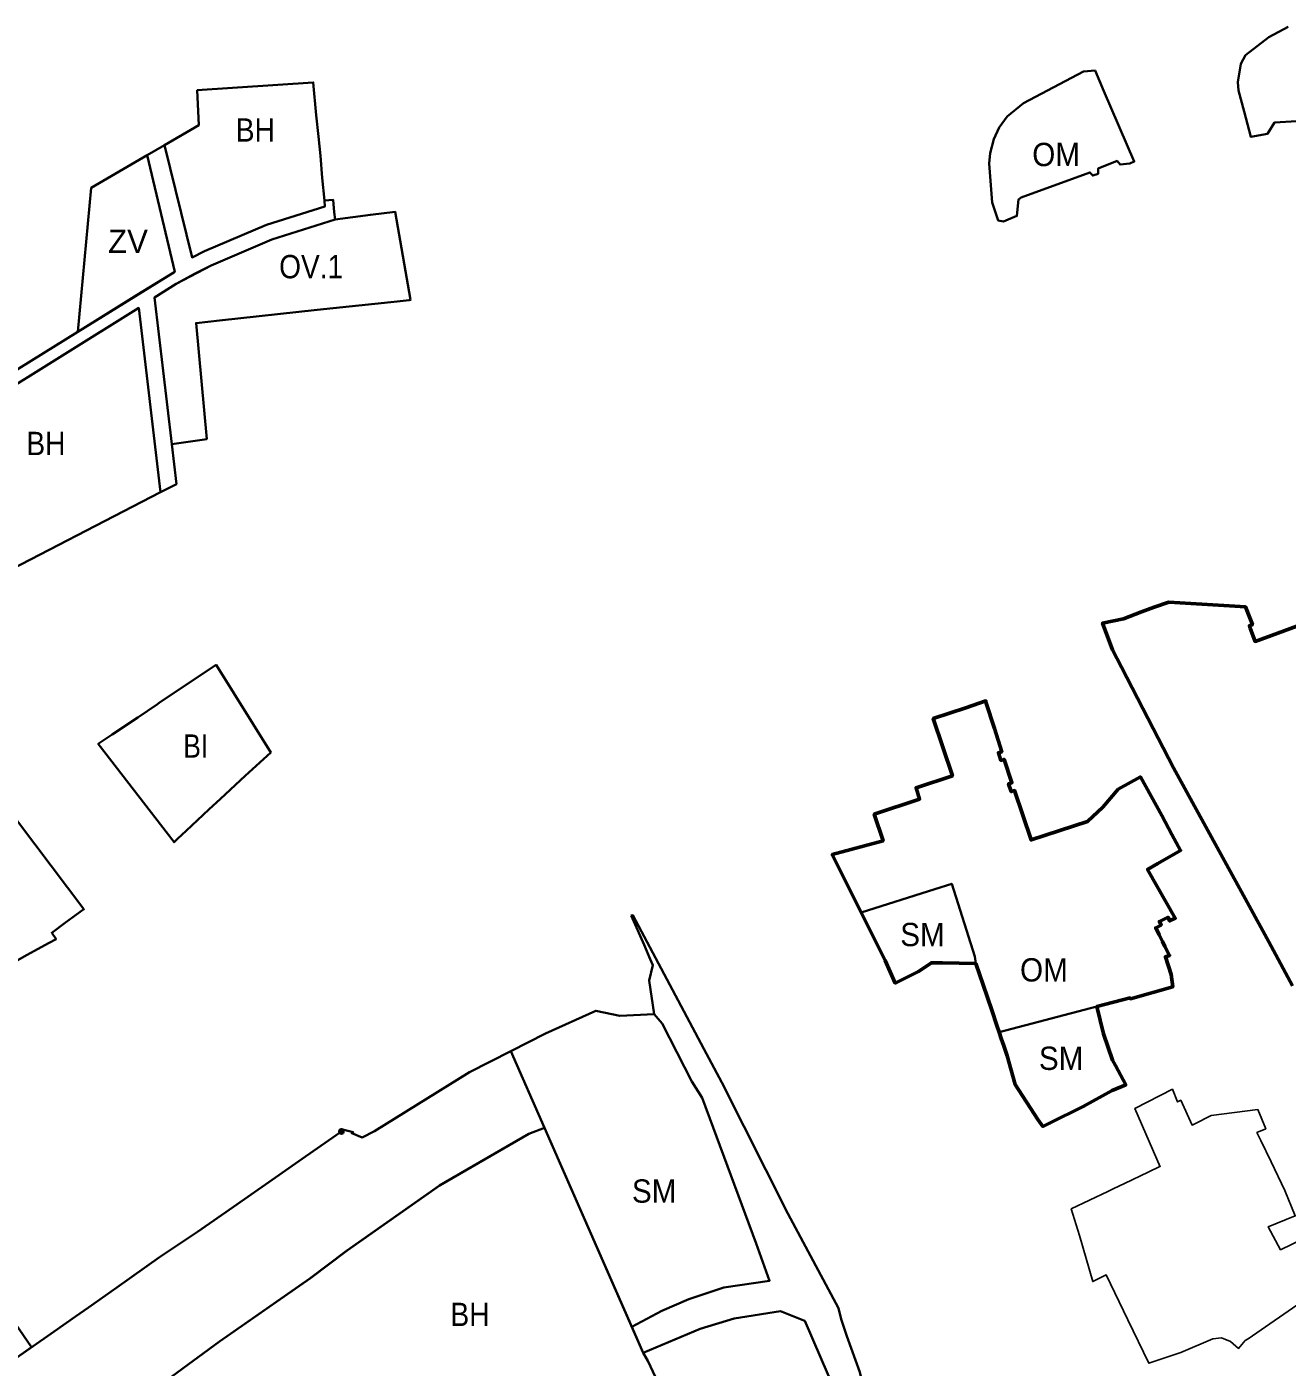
# Model space of a CAD drawing. Extents: x -650276 to -642489, y -1074311 to -1066658.
# Drawn here: x -648077 to -647428, y -1071063 to -1070373 of the extents above; entities that cross this region are included whole.
import ezdxf

# ---------------------------------------------------------------- set-up
doc = ezdxf.new("R2010")
doc.units = 0
doc.header["$LTSCALE"] = 4.8
doc.header["$PDMODE"] = 32
doc.header["$PDSIZE"] = 2.4
for name, color, linetype, lineweight in [('1', 7, 'Continuous', 35), ('11', 7, 'Continuous', 35), ('12', 7, 'Continuous', 35), ('15', 7, 'Continuous', 35), ('17', 7, 'Continuous', 35), ('18', 7, 'Continuous', 35), ('2', 7, 'Continuous', 35), ('40', 7, 'Continuous', 35), ('60', 7, 'Continuous', 53), ('61', 7, 'Continuous', 25)]:
    doc.layers.add(name, color=color, linetype=linetype, lineweight=lineweight)
doc.layers.add('62', color=7, linetype='Continuous')

msp = doc.modelspace()

# ---------------------------------------------------------------- linework, layer by layer
at = {"layer": '1'}
for points in [[(-647991.539, -1070492.016), (-647985.19, -1070488.804), (-647953.251, -1070475.276), (-647923.247, -1070465.749), (-647923.53, -1070462.75), (-647924.63, -1070451.09), (-647925.5, -1070439.63), (-647926.53, -1070429.76), (-647927.67, -1070418.74), (-647929.24, -1070401.97), (-647988.86, -1070405.95), (-647988.11, -1070423.93), (-648005.668, -1070434.145)], [(-648098.637, -1070659.682), (-648007.838, -1070612.851), (-648019, -1070518), (-648135.47, -1070590.61), (-648105.98, -1070645.91)], [(-648001.922, -1071067.83), (-647977.41, -1071049.74), (-647930.7, -1071017.18), (-647911.838, -1071002.919), (-647864.03, -1070969.3), (-647864.03, -1070969.3), (-647818.33, -1070942.91), (-647810.243, -1070939.825), (-647759.52, -1071055.67), (-647757.19, -1071059.66), (-647742.64, -1071090.72), (-647726.74, -1071122.48), (-647742.35, -1071129.43), (-647775.982, -1071148.001), (-647775.982, -1071148.001), (-647875.939, -1071221.104)]]:
    msp.add_lwpolyline(points, close=True, dxfattribs=at)
at = {"layer": '11'}
msp.add_lwpolyline([(-647927.14, -1070519), (-647889.27, -1070514.92), (-647886.09, -1070514.58), (-647879.89, -1070513.91), (-647879.16, -1070513.83), (-647887.08, -1070468.54), (-647899.87, -1070470.04), (-647917.98, -1070472.47), (-647950.48, -1070482.79), (-647981.81, -1070496.06), (-647990.295, -1070500.352), (-647999.756, -1070505.655), (-648010.831, -1070512.588), (-648002, -1070588), (-647984.03, -1070585.46), (-647989.5, -1070525.73), (-647977.41, -1070524.43)], close=True, dxfattribs=at)
at = {"layer": '12'}
msp.add_lwpolyline([(-647515.73, -1070442.32), (-647514.23, -1070444.18), (-647509.22, -1070443.62), (-647506.95, -1070442.71), (-647522.54, -1070406.51), (-647527.1, -1070395.72), (-647533.1, -1070396.26), (-647564.01, -1070412.59), (-647572.37, -1070419.41), (-647576.48, -1070425.09), (-647579.22, -1070431.05), (-647581.04, -1070438.4), (-647581.54, -1070443.7), (-647580.1, -1070463.69), (-647576.92, -1070473), (-647574.28, -1070473.46), (-647567.32, -1070470.66), (-647566.55, -1070462.22), (-647565.11, -1070461.12), (-647529.74, -1070448.27), (-647528.28, -1070449.87), (-647525.54, -1070448.89), (-647525.45, -1070446.21)], close=True, dxfattribs=at)
msp.add_lwpolyline([(-647515.73, -1070442.32), (-647514.23, -1070444.18), (-647509.22, -1070443.62), (-647506.95, -1070442.71), (-647522.54, -1070406.51), (-647527.1, -1070395.72), (-647533.1, -1070396.26), (-647564.01, -1070412.59), (-647572.37, -1070419.41), (-647576.48, -1070425.09), (-647579.22, -1070431.05), (-647581.04, -1070438.4), (-647581.54, -1070443.7), (-647580.1, -1070463.69), (-647576.92, -1070473), (-647574.28, -1070473.46), (-647567.32, -1070470.66), (-647566.55, -1070462.22), (-647565.11, -1070461.12), (-647529.74, -1070448.27), (-647528.28, -1070449.87), (-647525.54, -1070448.89), (-647525.45, -1070446.21)], close=True, dxfattribs=at)
msp.add_lwpolyline([(-647515.73, -1070442.32), (-647514.23, -1070444.18), (-647509.22, -1070443.62), (-647506.95, -1070442.71), (-647522.54, -1070406.51), (-647527.1, -1070395.72), (-647533.1, -1070396.26), (-647564.01, -1070412.59), (-647572.37, -1070419.41), (-647576.48, -1070425.09), (-647579.22, -1070431.05), (-647581.04, -1070438.4), (-647581.54, -1070443.7), (-647580.1, -1070463.69), (-647576.92, -1070473), (-647574.28, -1070473.46), (-647567.32, -1070470.66), (-647566.55, -1070462.22), (-647565.11, -1070461.12), (-647529.74, -1070448.27), (-647528.28, -1070449.87), (-647525.54, -1070448.89), (-647525.45, -1070446.21)], close=True, dxfattribs=at)
for points in [[(-647569.92, -1070762.24), (-647573.88, -1070750.25), (-647575.58, -1070750.83), (-647576.81, -1070746.86), (-647575.09, -1070746.33), (-647578.79, -1070734.33), (-647583.38, -1070720.9), (-647583.22, -1070720.2), (-647593.6, -1070723.68), (-647610.33, -1070729.28), (-647600.53, -1070758.65), (-647619.2, -1070764.85), (-647617.36, -1070770.69)], [(-647636.12, -1070792.13), (-647654.89, -1070797.23), (-647662.26, -1070799.23), (-647650.908, -1070822.34), (-647647.405, -1070829.08), (-647609.58, -1070817.06), (-647600.8, -1070814.27), (-647588.89, -1070851.67), (-647588.4, -1070855.25), (-647584.6, -1070866.3), (-647580.22, -1070879.3), (-647578.703, -1070883.851), (-647578.703, -1070883.851), (-647576.469, -1070890.564), (-647526.13, -1070877.41), (-647509.1, -1070872.96), (-647508.96, -1070873.41), (-647487.16, -1070867.32), (-647487.91, -1070860.91), (-647490.92, -1070851.82), (-647488.8, -1070851.12), (-647494.1, -1070840.58), (-647495.93, -1070836.86), (-647493.16, -1070835.5), (-647494.03, -1070833.64), (-647489.55, -1070831.53), (-647488.75, -1070833.37), (-647485.9, -1070832), (-647500.07, -1070806.87), (-647500.07, -1070806.87), (-647483.16, -1070797.07), (-647492.81, -1070779.18), (-647492.81, -1070779.18), (-647497.227, -1070771.165), (-647503.76, -1070759.31), (-647514.49, -1070764.93), (-647517.61, -1070767.89), (-647523.07, -1070774.86), (-647531.05, -1070782.23), (-647560.06, -1070791.72), (-647566.26, -1070773.148)], [(-647570.27, -1070766.86), (-647571.63, -1070762.82), (-647569.92, -1070762.24)], [(-647566.26, -1070773.148), (-647568.55, -1070766.29), (-647570.27, -1070766.86)], [(-647617.36, -1070770.69), (-647619.12, -1070771.28), (-647640.66, -1070778.47), (-647636.12, -1070792.13)]]:
    msp.add_lwpolyline(points, dxfattribs=at)
at = {"layer": '15'}
for points in [[(-648007.838, -1070612.851), (-647999.588, -1070608.596), (-648002, -1070588), (-648010.831, -1070512.588), (-647999.756, -1070505.655), (-647981.81, -1070496.06), (-647950.48, -1070482.79), (-647917.98, -1070472.47), (-647918.54, -1070468.61), (-647918.95, -1070462.36), (-647923.53, -1070462.75), (-647923.247, -1070465.749), (-647953.251, -1070475.276), (-647985.19, -1070488.804), (-647991.539, -1070492.016), (-648005.668, -1070434.145), (-648014.63, -1070439.36), (-648000.442, -1070499.336), (-648019.789, -1070511.293), (-648050.38, -1070530.2), (-648122.57, -1070575), (-648137.78, -1070586.25), (-648135.47, -1070590.61), (-648019, -1070518)], [(-648092.72, -1071025.89), (-648104.12, -1071033.78), (-648085.73, -1071060.92), (-648074.12, -1071052.75)]]:
    msp.add_lwpolyline(points, close=True, dxfattribs=at)
for points in [[(-647659.01, -1071032.66), (-647685.1, -1070983.93), (-647719.06, -1070916.45), (-647728.35, -1070899.11), (-647764.84, -1070830.47), (-647765.72, -1070830.64)], [(-647765.72, -1070830.64), (-647759.08, -1070845.74), (-647755.87, -1070853.02), (-647754.6, -1070856.11), (-647756.45, -1070863.95), (-647753.81, -1070881.3)], [(-647753.81, -1070881.3), (-647749.75, -1070886.1), (-647734.48, -1070915.94), (-647729.27, -1070924.35), (-647701.45, -1070999.4)], [(-647701.45, -1070999.4), (-647694.54, -1071018.549), (-647718, -1071022), (-647736, -1071028), (-647750, -1071034), (-647765.408, -1071042.223), (-647759.52, -1071055.67), (-647730.17, -1071043.21), (-647712.74, -1071037.99), (-647688.9, -1071034.18), (-647676.96, -1071039.014)], [(-647640.727, -1071095.819), (-647648.106, -1071065.551), (-647654.747, -1071047.095), (-647657.699, -1071038.232), (-647659.01, -1071032.66)], [(-647676.96, -1071039.014), (-647676.9, -1071039.03), (-647676.45, -1071039.22), (-647656.443, -1071085.369), (-647658.55, -1071097.02), (-647669.02, -1071102.33), (-647667.35, -1071106.38), (-647655.47, -1071100.98), (-647640.727, -1071095.819)]]:
    msp.add_lwpolyline(points, dxfattribs=at)
at = {"layer": '17'}
msp.add_lwpolyline([(-647427.8, -1070373.32), (-647437.76, -1070378.66), (-647449.69, -1070387.83), (-647452.17, -1070392.38), (-647453.71, -1070401.81), (-647453.35, -1070406.09), (-647450.51, -1070416.96), (-647446.93, -1070429.99), (-647438.45, -1070428.47), (-647434.85, -1070422.64), (-647423.38, -1070421.87)], dxfattribs=at)
at = {"layer": '18'}
for points in [[(-647588.4, -1070855.25), (-647588.89, -1070851.67), (-647600.8, -1070814.27), (-647609.58, -1070817.06), (-647647.405, -1070829.08)], [(-647647.405, -1070829.08), (-647635.11, -1070853.786), (-647629.92, -1070865.35), (-647618.01, -1070859.42), (-647611.3, -1070854.9), (-647605.64, -1070854.99), (-647588.4, -1070855.25)], [(-647511.37, -1070917.79), (-647516.66, -1070907.8), (-647518.12, -1070905.05), (-647522.74, -1070891.48), (-647526.13, -1070877.41), (-647576.469, -1070890.564)], [(-647576.469, -1070890.564), (-647576.43, -1070890.68), (-647575.35, -1070893.91), (-647574.09, -1070897.7), (-647572.32, -1070902.72), (-647568.2, -1070917.54), (-647556.52, -1070935.59), (-647553.94, -1070939.11)], [(-647553.94, -1070939.11), (-647553.94, -1070939.11), (-647550.59, -1070937.45), (-647533.31, -1070928.79), (-647518.35, -1070920.62)], [(-647518.35, -1070920.62), (-647514.7, -1070918.79), (-647511.37, -1070917.79)]]:
    msp.add_lwpolyline(points, dxfattribs=at)
msp.add_lwpolyline([(-647736, -1071028), (-647718, -1071022), (-647694.54, -1071018.549), (-647701.45, -1070999.4), (-647729.27, -1070924.35), (-647734.48, -1070915.94), (-647749.75, -1070886.1), (-647753.81, -1070881.3), (-647771.47, -1070882.27), (-647783.95, -1070879.58), (-647809.74, -1070891.31), (-647827.527, -1070900.351), (-647810.243, -1070939.825), (-647765.408, -1071042.223), (-647750, -1071034)], close=True, dxfattribs=at)
at = {"layer": '2'}
for points in [[(-648032.601, -1070737.472), (-648039.82, -1070742.33), (-648000.85, -1070792.88), (-647999.06, -1070791.2), (-647994.63, -1070787.05), (-647994.63, -1070787.05), (-647982.89, -1070776.05), (-647976.97, -1070770.51), (-647964.21, -1070758.77), (-647951.11, -1070746.78), (-647979.17, -1070701.65), (-648008.28, -1070720.96), (-648009.29, -1070721.79), (-648019.49, -1070728.65)], [(-648114.77, -1070788.08), (-648125.2, -1070794.79), (-648083.65, -1070854.89), (-648076.73, -1070851.07), (-648074.41, -1070849.79), (-648072.59, -1070848.79), (-648065.35, -1070844.8), (-648061.52, -1070842.68), (-648063.76, -1070839.49), (-648056.61, -1070834.26), (-648047.17, -1070827.35), (-648089.27, -1070771.57), (-648104.78, -1070781.65)]]:
    msp.add_lwpolyline(points, close=True, dxfattribs=at)
msp.add_lwpolyline([(-648001.922, -1071067.83), (-647977.41, -1071049.74), (-647930.96, -1071017.383), (-647912.11, -1071003.11), (-647864.29, -1070969.503), (-647818.33, -1070942.91), (-647810.243, -1070939.825), (-647827.527, -1070900.351), (-647848.89, -1070911.21), (-647897.76, -1070941.62), (-647904.13, -1070944.78), (-647909.42, -1070942.63), (-647908.63, -1070942.1), (-647913.45, -1070940.79), (-647934.9, -1070955.87), (-647952.01, -1070967.82), (-647970.19, -1070980.45), (-647988.81, -1070993.27), (-648008.34, -1071006.32), (-648030.24, -1071021.91), (-648044.82, -1071032.25), (-648051.48, -1071036.97), (-648062.53, -1071044.59), (-648085.73, -1071060.92)], dxfattribs=at)
msp.add_point((-647914.73, -1070941.682), dxfattribs=at)
at = {"layer": '40'}
msp.add_lwpolyline([(-648014.63, -1070439.36), (-648000.442, -1070499.336), (-648050.38, -1070530.2), (-648043.43, -1070456.12)], close=True, dxfattribs=at)
at = {"layer": '60'}
msp.add_lwpolyline([(-647418.28, -1070679.89), (-647444.78, -1070689.6), (-647447.31, -1070682.72), (-647447.76, -1070681.5), (-647446.22, -1070680.91), (-647447.58, -1070677.36), (-647449.69, -1070671.81), (-647455.17, -1070671.48), (-647489.21, -1070669.41), (-647496.64, -1070671.93), (-647503.3, -1070674.3), (-647512.51, -1070677.98), (-647523.27, -1070680.11), (-647518.19, -1070693.93), (-647513.59, -1070702.8), (-647502.59, -1070724.13), (-647486.84, -1070754.54), (-647464.3, -1070795.6), (-647448.84, -1070823.79), (-647437.79, -1070844.12), (-647425.58, -1070866.7)], dxfattribs=at)
msp.add_lwpolyline([(-647588.4, -1070855.25), (-647584.6, -1070866.3), (-647580.22, -1070879.3), (-647577.59, -1070887.19), (-647576.43, -1070890.68), (-647575.35, -1070893.91), (-647574.09, -1070897.7), (-647572.32, -1070902.72), (-647568.2, -1070917.54), (-647556.52, -1070935.59), (-647553.94, -1070939.11), (-647550.59, -1070937.45), (-647533.31, -1070928.79), (-647518.35, -1070920.62), (-647511.37, -1070917.79), (-647516.66, -1070907.8), (-647518.12, -1070905.05), (-647522.74, -1070891.48), (-647526.13, -1070877.41), (-647509.1, -1070872.96), (-647508.96, -1070873.41), (-647487.16, -1070867.32), (-647487.91, -1070860.91), (-647490.92, -1070851.82), (-647488.8, -1070851.12), (-647491.19, -1070846.49), (-647492.48, -1070843.88), (-647494.1, -1070840.58), (-647495.93, -1070836.86), (-647493.16, -1070835.5), (-647494.03, -1070833.64), (-647489.55, -1070831.53), (-647488.75, -1070833.37), (-647485.9, -1070832), (-647500.07, -1070806.87), (-647500.07, -1070806.87), (-647494.88, -1070803.86), (-647483.16, -1070797.07), (-647487.67, -1070788.86), (-647492.81, -1070779.18), (-647503.76, -1070759.31), (-647515.216, -1070765.619), (-647523.07, -1070774.86), (-647531.05, -1070782.23), (-647560.06, -1070791.72), (-647568.55, -1070766.29), (-647570.27, -1070766.86), (-647571.63, -1070762.82), (-647569.92, -1070762.24), (-647573.88, -1070750.25), (-647575.58, -1070750.83), (-647576.81, -1070746.86), (-647575.09, -1070746.33), (-647578.79, -1070734.33), (-647583.38, -1070720.9), (-647583.22, -1070720.2), (-647593.6, -1070723.68), (-647610.33, -1070729.28), (-647600.53, -1070758.65), (-647619.2, -1070764.85), (-647617.36, -1070770.69), (-647640.66, -1070778.47), (-647636.12, -1070792.13), (-647662.26, -1070799.23), (-647635.11, -1070853.786), (-647629.92, -1070865.35), (-647618.01, -1070859.42), (-647611.3, -1070854.9), (-647605.64, -1070854.99)], close=True, dxfattribs=at)
at = {"layer": '61'}
msp.add_lwpolyline([(-647418.88, -1071028.01), (-647448.32, -1071048.39), (-647449.88, -1071049.31), (-647453.32, -1071053.37), (-647457.4, -1071049.84), (-647462.03, -1071047.83), (-647466.48, -1071048.33), (-647483.08, -1071055.41), (-647489.7, -1071057.66), (-647499.39, -1071060.95), (-647510.18, -1071038.65), (-647521.36, -1071015.52), (-647528.27, -1071018.94), (-647535.19, -1070995.23), (-647539.38, -1070981.6), (-647520.58, -1070972.61), (-647517.43, -1070971.1), (-647511.96, -1070968.48), (-647499.8, -1070962.67), (-647493.79, -1070959.8), (-647493.71, -1070959.89), (-647506.58, -1070929.86), (-647487.33, -1070919.95), (-647484.78, -1070926.54), (-647483.02, -1070925.66), (-647477.21, -1070938.44), (-647475.82, -1070937.77), (-647467.47, -1070933.53), (-647443.36, -1070930.41), (-647439.33, -1070940.28), (-647443.84, -1070942.26), (-647442.33, -1070945.38), (-647441.9, -1070946.28), (-647436.58, -1070957.29), (-647429.44, -1070972.06), (-647424.16, -1070985.19), (-647438.05, -1070990.74), (-647431.74, -1071002.56), (-647413.35, -1070993.67)], dxfattribs=at)

# ---------------------------------------------------------------- texts
at = {"layer": '62'}
for s, width, p in [('BH', 0.9, (-647969.069, -1070432.39)), ('OM', 0.95, (-647559.43, -1070445.015)), ('OV.1', 0.9, (-647946.769, -1070502.709)), ('BH', 0.9, (-648076.769, -1070593.709)), ('BI', 0.85, (-647996.127, -1070749.398)), ('SM', 0.95, (-647627.328, -1070846.374)), ('OM', 0.95, (-647565.708, -1070864.552)), ('SM', 0.95, (-647556.006, -1070910.054)), ('SM', 0.95, (-647765.328, -1070978.374)), ('BH', 0.9, (-647858.64, -1071041.819))]:
    msp.add_text(s, height=12, dxfattribs=dict(at, width=width)).set_placement(p)
msp.add_text('ZV', height=12, dxfattribs=at).set_placement((-648034.769, -1070489.709))

doc.saveas('drawing.dxf')
